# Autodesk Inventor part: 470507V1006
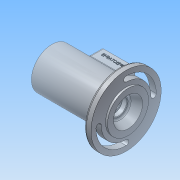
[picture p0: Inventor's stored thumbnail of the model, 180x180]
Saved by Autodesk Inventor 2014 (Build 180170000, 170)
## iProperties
Created: 2017-05
Part Number: 470507V1006
Material: 알루미늄 6061
Document SubType Name: Modeling
Designer: NET
Density: 2.71 g/cm^3
Appearance: 알루미늄 - 평지
Mass: 683.255 g
Surface Area: 619.43 cm^2
Volume: 252.123 cm^3
Author: NET
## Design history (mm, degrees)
sketch "스케치1"
  geometry: L1 (0, 0)-(0, 31); L2 (0, 31)-(102, 31); L3 (102, 31)-(102, 53); L4 (102, 53)-(112, 53); L5 (112, 53)-(112, 31); L6 (112, 31)-(115, 31); L7 (115, 31)-(115, 0); L8 (115, 0)-(0, 0); L9 (115, 22)-(102.818, 16.779); L10 (101, 14.022)-(101, 12.904); L11 (100.3, 12.5)-(94, 12.5); L12 (93.7, 12.2)-(93.7, 10); L13 (93.7, 10)-(91, 10); L14 (91, 10)-(91, 13.5); L15 (88, 16.5)-(86, 16.5); L16 (86, 16.5)-(86, 17.2); L17 (85.7, 17.5)-(74.7, 17.5); L18 (74.7, 17.5)-(74.89, 22.894); L19 (71.892, 26)-(40, 26); L20 (37, 23)-(37, 17.5); L21 (37, 17.5)-(26, 17.5); L22 (26, 17.5)-(26, 18.5); L23 (26, 18.5)-(24.25, 18.5); L24 (21, 20)-(12, 20); L25 (100.3, 12.5)-(101, 12.904); L26 (24.25, 18.5)-(24.25, 17.5); L27 (24.25, 17.5)-(21, 17.5); L28 (21, 17.5)-(21, 20); L29 (12, 20)-(12, 24); L30 (12, 24)-(9, 24); L31 (9, 24)-(9, 20); L32 (9, 20)-(0, 20); A1 r 0.3 centre (94, 12.2) between (94, 12.5) and (93.7, 12.2); A2 r 3 centre (104, 14.022) between (102.818, 16.779) and (101, 14.022); A3 r 3 centre (88, 13.5) between (91, 13.5) and (88, 16.5); A4 r 0.3 centre (85.7, 17.2) between (86, 17.2) and (85.7, 17.5); A5 r 3 centre (71.892, 23) between (74.89, 22.894) and (71.892, 26); A6 r 3 centre (40, 23) between (40, 26) and (37, 23); 4 further points
  constraints: 64 end point, 14 tangent, 12 point on circle, 8 point on line, 8 vertical, 7 horizontal, 6 centre point, 6 parallel, 2 equal radius, 1 coincident
  dimensions: "d0" = 3 distance of L5.end L6.end; "d1" = 115 distance of L1.end L6.end; "d2" = 10 distance of L3.end L4.end; "d3" = 62 diameter of L6 L8; "d4" = 62 diameter of L2 L8; "d5" = 106 diameter of L4 L8; "d6" = 44 diameter of L9.start L8; "d7" = 32 diameter of point (101, 16) L8; "d8" = 14 horizontal distance of L9.start point (101, 16); "d10" = 30 deg angle of L11 L25; "d11" = 0.7 horizontal distance of L10.end L11.start; "d12" = 0.3 radius of A1; "d13" = 7.3 horizontal distance of L12.end L10.end; "d14" = 2.7 distance of L12.end L13.end; "d15" = 25 diameter of L11 L8; "d16" = 20 diameter of L13 L8; "d17" = 3 radius of A2; "d18" = 0.3 radius of A4; "d19" = 5 horizontal distance of L13.end L15.end; "d20" = 11 distance of L17.start L17.end; "d21" = 33 diameter of L15 L8; "d22" = 35 diameter of L17 L8; "d23" = 52 diameter of L19 L8; "d24" = 38 distance of point (75, 26) point (37, 26); "d25" = 3 radius of A5; "d26" = 11 distance of L20.end L21.end; "d27" = 1.75 distance of L22.end L23.end; "d28" = 37 diameter of L23 L8; "d29" = 35 diameter of L21 L8; "d30" = 35 diameter of L27 L8; "d31" = 40 diameter of L24 L8; "d32" = 60 horizontal distance of L15.end L21.end; "d33" = 3 distance of L29.end L30.end; "d34" = 12 horizontal distance of L32.end L29.end; "d35" = 21 distance of L32.end L24.start; "d36" = 48 diameter of L30 L8
revolve "회전1" sketch "스케치1" stored, may be unused: angle "d37" = 90 deg
sketch "스케치4"
  geometry: C1 r 20 at (0, 0) reference; 3 further points
  constraints: 2 vertical alignment, 1 coincident, 1 other
node "작업 평면4"
  node "작업 평면3"
sketch "스케치5"
  geometry: L1 (-31, -20)-(-81, -20); L2 (-81, -20)-(-81, 20); L3 (-81, 20)-(-31, 20); L4 (-31, 20)-(-31, -20); L5 (-43, -11)-(-69, -11); L6 (-72, -8)-(-72, 8); L7 (-69, 11)-(-43, 11); L8 (-40, 8)-(-40, -8); L9 (0, 31)-(0, -31) reference; A1 r 3 centre (-69, 8) between (-69, 11) and (-72, 8); A2 r 3 centre (-69, -8) between (-72, -8) and (-69, -11); A3 r 3 centre (-43, 8) between (-40, 8) and (-43, 11); A4 r 3 centre (-43, -8) between (-43, -11) and (-40, -8); 10 further points
  constraints: 16 end point, 8 point on circle, 8 point on line, 8 tangent, 5 midpoint, 4 centre point, 4 horizontal, 4 vertical, 3 equal radius, 2 horizontal alignment, 1 vertical alignment
  dimensions: "d45" = 50 distance of L2.end L3.end; "d46" = 32 distance of point (-72, 11) point (-40, 11); "d47" = 40 distance of L3.end L1.start; "d48" = 22 distance of point (-40, 11) point (-40, -11); "d49" = 56 distance from line of L9 point (-56, 11); "d99" = 3 radius of A1
extrude "돌출1" join sketch "스케치5" stored distance "d50" = 10; taper "d51" = 0 deg
fillet "모깎기1" dims "d54" = 3
fillet "모깎기2" dims "d55" = 3
fillet "모깎기3" dims "d56" = 3
fillet "모깎기4" dims "d57" = 3
sketch "스케치6"
  geometry: C1 r 53 at (0, 0) reference; C2 r 31 at (0, 0) reference; A1 r 4 centre (0, 41.5) between (0, 37.5) and (0, 45.5); A2 r 4 centre (-41.5, 0) between (-45.5, 0) and (-37.5, 0); A3 r 4 centre (41.5, 0) between (45.5, 0) and (37.5, 0); A4 r 4 centre (0, -41.5) between (0, -37.5) and (0, -45.5); A5 r 37.5 centre (0, 0) between (0, 37.5) and (-37.5, 0); A6 r 37.5 centre (0, 0) between (0, -37.5) and (37.5, 0); A7 r 45.5 centre (0, 0) between (0, 45.5) and (-45.5, 0); A8 r 45.5 centre (0, 0) between (0, -45.5) and (45.5, 0)
  constraints: 16 point on circle, 8 centre point, 4 tangent, 2 horizontal alignment, 2 vertical alignment, 1 coincident, 1 concentric
  dimensions: "d61" = 45.5 radius of A7; "d62" = 37.5 radius of A5; "d63" = 37.5 radius of A6; "d64" = 45.5 radius of A8; "d65" = 4 radius of A3; "d66" = 4 radius of A4; "d67" = 4 radius of A1; "d68" = 4 radius of A2
extrude "돌출3" cut sketch "스케치6" distance "d69" = 13; taper "d70" = 0 deg
extrude "돌출4" cut sketch "스케치6" distance "d71" = 13; taper "d72" = 0 deg
hole "구멍1" diameter "d75" = 40.376; stored, may be unused: countersink angle "d79" = 90 deg, drill point angle "d81" = 118 deg; dims "d73" = 10, "d74" = 10, "d76" = 9, "d77" = 4, "d78" = 2, "d80" = 9
chamfer "모따기1" distance "d82" = 1; stored, may be unused: second distance "d83" = 2, angle "d84" = 45 deg
sketch "스케치7"
  geometry: L1 (44, 0)-(0, 0) reference; L2 (-34, -75)-(-34, -13) reference; 2 further points
  constraints: 1 other
  dimensions: "d85" = 56 distance from line of L2 point (22, -8); "d86" = 8 distance from line of point (22, -8) L1
feature "엠보싱1" sketch "스케치7" dims "d16" = 20, "d87" = 0.5, "d88" = 0
sketch "스케치8"
  geometry: L1 (34, 20)-(78, 20) reference; L2 (31, -17)-(31, 17) reference; L3 (81, 17)-(81, -17) reference; L4 (76.5, -15.5)-(35.36, -15.5); L5 (35.36, -15.5)-(35.5, 15.5); L6 (35.5, 15.5)-(76.5, 15.5); L7 (76.5, 15.5)-(76.5, -15.5); 11 further points
  constraints: 8 end point, 6 coincident, 4 midpoint, 2 horizontal, 1 horizontal alignment, 1 parallel, 1 vertical alignment
  dimensions: "d89" = 41 distance of L5.end L6.end; "d90" = 31 distance of L6.end L4.start; "d91" = 0.258944 deg angle of L3 L5
hole "구멍2" sketch "스케치8" at (76.5, -15.5), (35.36, -15.5), (35.5, 15.5), (76.5, 15.5) diameter "d92" = 2.459; stored, may be unused: countersink angle "d96" = 90 deg, drill point angle "d98" = 118 deg; dims "d93" = 6, "d94" = 4, "d95" = 2, "d97" = 8
extrude "돌출5" cut sketch "스케치5" stored distance "d100" = 13; taper "d101" = 0 deg
node "솔리드1"
node "작업 평면2"
other parameters: "d43" = -31, "d44" = 44, "d58" = 83, "d59" = 91, "d60" = 75
